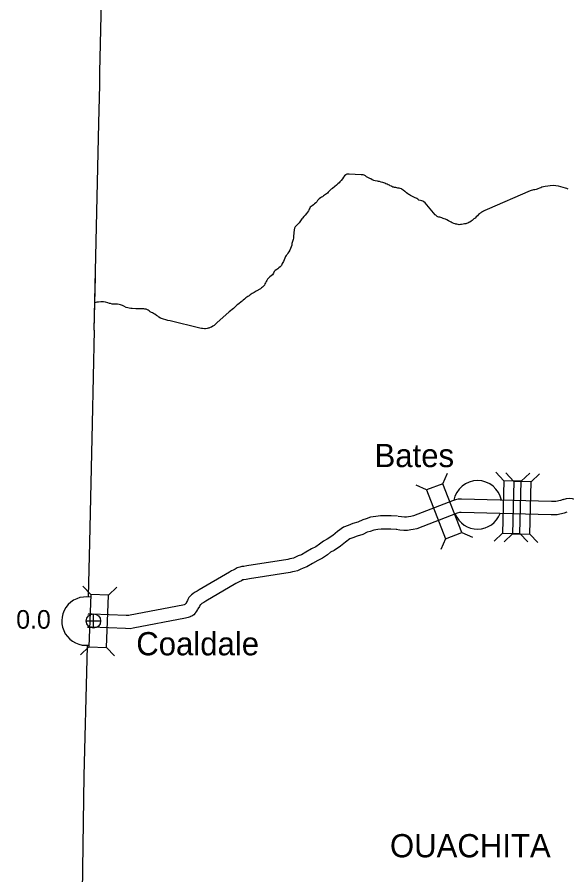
# Model space of a CAD drawing. Extents: x -939622 to -934245, y 1383184 to 1385301.
# Drawn here: x -936457.6 to -936420.2, y 1384298.8 to 1384357.3 of the extents above; entities that cross this region are included whole.
import ezdxf

# ---------------------------------------------------------------- set-up
doc = ezdxf.new("R2010")
doc.units = 0
for name, color, linetype in [('Level 1', 7, 'Continuous'), ('Level 10', 7, 'Continuous'), ('Level 2', 7, 'Continuous'), ('Level 20', 7, 'Continuous'), ('Level 24', 7, 'Continuous'), ('Level 25', 7, 'Continuous'), ('Level 26', 7, 'Continuous'), ('Level 8', 7, 'Continuous')]:
    doc.layers.add(name, color=color, linetype=linetype)

msp = doc.modelspace()

# ---------------------------------------------------------------- linework, layer by layer
at = {"layer": 'Level 1'}
for points in [[(-936452.361, 1384335.927), (-936452.042, 1384350.048), (-936451.974, 1384352.646), (-936451.962, 1384353.514), (-936451.499, 1384373.877)], [(-936452.361, 1384335.927), (-936452.279, 1384339.578)], [(-936452.361, 1384335.927), (-936452.497, 1384329.574), (-936452.676, 1384321.469), (-936452.759, 1384317.789)], [(-936452.835, 1384314.397), (-936452.855, 1384313.527), (-936453.061, 1384305.572)], [(-936453.061, 1384305.572), (-936453.175, 1384297.647)]]:
    msp.add_lwpolyline(points, dxfattribs=at)
at = {"layer": 'Level 10'}
for points in [[(-936420.42, 1384324.397), (-936420.61, 1384324.334), (-936420.935, 1384324.255), (-936421.229, 1384324.26), (-936427.346, 1384324.415), (-936427.412, 1384324.417), (-936427.566, 1384324.419), (-936427.749, 1384324.374), (-936427.952, 1384324.301), (-936430.624, 1384323.273), (-936430.801, 1384323.243), (-936430.948, 1384323.214), (-936431.093, 1384323.191), (-936431.225, 1384323.19), (-936431.437, 1384323.21), (-936431.656, 1384323.246)], [(-936420.42, 1384324.397), (-936420.207, 1384324.458), (-936420.026, 1384324.478), (-936419.812, 1384324.458), (-936419.656, 1384324.424), (-936419.471, 1384324.371), (-936419.305, 1384324.322), (-936419.188, 1384324.302), (-936418.95, 1384324.288), (-936418.616, 1384324.32)], [(-936431.697, 1384323.25), (-936432.133, 1384323.281), (-936432.55, 1384323.274), (-936432.867, 1384323.285), (-936433.176, 1384323.236), (-936433.54, 1384323.191), (-936433.838, 1384323.072), (-936434.065, 1384323.017), (-936434.399, 1384322.862), (-936434.75, 1384322.753), (-936435.066, 1384322.621), (-936435.38, 1384322.507), (-936435.782, 1384322.208), (-936436.116, 1384321.953), (-936436.491, 1384321.7), (-936436.753, 1384321.562), (-936437.009, 1384321.359), (-936437.276, 1384321.176), (-936437.568, 1384321.03), (-936437.938, 1384320.81), (-936438.254, 1384320.629), (-936438.471, 1384320.554), (-936438.697, 1384320.441), (-936438.794, 1384320.402), (-936438.912, 1384320.373), (-936439.042, 1384320.345), (-936439.182, 1384320.315), (-936441.961, 1384319.884), (-936442.159, 1384319.839), (-936442.304, 1384319.82), (-936442.437, 1384319.796), (-936442.626, 1384319.735), (-936442.75, 1384319.657), (-936442.906, 1384319.588), (-936443.007, 1384319.528), (-936443.149, 1384319.454), (-936445.208, 1384318.239), (-936445.347, 1384318.156), (-936445.524, 1384318.06), (-936445.631, 1384317.973), (-936445.731, 1384317.909), (-936445.81, 1384317.827), (-936445.909, 1384317.719), (-936445.98, 1384317.578), (-936446, 1384317.514), (-936446.08, 1384317.409), (-936446.128, 1384317.298), (-936446.137, 1384317.283), (-936446.174, 1384317.237), (-936446.18, 1384317.235), (-936446.221, 1384317.219), (-936446.318, 1384317.196), (-936449.906, 1384316.513), (-936449.999, 1384316.489), (-936450.185, 1384316.501), (-936452.494, 1384316.586), (-936452.642, 1384316.592), (-936452.771, 1384316.572), (-936452.774, 1384316.571)], [(-936420.188, 1384323.525), (-936420.362, 1384323.468), (-936420.835, 1384323.353), (-936421.248, 1384323.36), (-936427.372, 1384323.515), (-936427.432, 1384323.517), (-936427.463, 1384323.518), (-936427.489, 1384323.511), (-936427.638, 1384323.458), (-936430.385, 1384322.401), (-936430.638, 1384322.358), (-936430.789, 1384322.328), (-936431.02, 1384322.291), (-936431.266, 1384322.29), (-936431.551, 1384322.317), (-936431.8, 1384322.357)], [(-936431.759, 1384322.352), (-936432.156, 1384322.38), (-936432.559, 1384322.373), (-936432.812, 1384322.382), (-936433.051, 1384322.344), (-936433.314, 1384322.312), (-936433.564, 1384322.212), (-936433.766, 1384322.163), (-936434.074, 1384322.02), (-936434.443, 1384321.906), (-936434.74, 1384321.782), (-936434.949, 1384321.706), (-936435.24, 1384321.489), (-936435.591, 1384321.222), (-936436.028, 1384320.927), (-936436.259, 1384320.805), (-936436.475, 1384320.634), (-936436.818, 1384320.398), (-936437.137, 1384320.239), (-936437.484, 1384320.033), (-936437.88, 1384319.806), (-936438.122, 1384319.723), (-936438.329, 1384319.618), (-936438.518, 1384319.544), (-936438.709, 1384319.496), (-936438.854, 1384319.465), (-936439.019, 1384319.43), (-936441.793, 1384318.999), (-936442.001, 1384318.952), (-936442.166, 1384318.93), (-936442.218, 1384318.921), (-936442.243, 1384318.913), (-936442.326, 1384318.861), (-936442.492, 1384318.787), (-936442.569, 1384318.741), (-936442.712, 1384318.667), (-936444.749, 1384317.464), (-936444.901, 1384317.374), (-936445.021, 1384317.309), (-936445.103, 1384317.242), (-936445.151, 1384317.212), (-936445.185, 1384317.099), (-936445.299, 1384316.949), (-936445.319, 1384316.902), (-936445.386, 1384316.779), (-936445.455, 1384316.695), (-936445.488, 1384316.649), (-936445.583, 1384316.544), (-936445.71, 1384316.448), (-936445.79, 1384316.423), (-936445.834, 1384316.404), (-936445.953, 1384316.357), (-936446.13, 1384316.315), (-936449.709, 1384315.634), (-936449.914, 1384315.581), (-936450.232, 1384315.602), (-936452.529, 1384315.686), (-936452.59, 1384315.689), (-936452.677, 1384315.675), (-936452.777, 1384315.67), (-936452.815, 1384315.667)]]:
    msp.add_lwpolyline(points, dxfattribs=at)
at = {"layer": 'Level 2'}
for points in [[(-936431.532, 1384345.594), (-936431.601, 1384345.607), (-936431.688, 1384345.62), (-936431.748, 1384345.637), (-936431.812, 1384345.659), (-936431.904, 1384345.663), (-936431.961, 1384345.676), (-936432.019, 1384345.69), (-936432.094, 1384345.721), (-936432.127, 1384345.744), (-936432.206, 1384345.779), (-936432.258, 1384345.81), (-936432.342, 1384345.847), (-936432.418, 1384345.884), (-936432.502, 1384345.918), (-936432.566, 1384345.953), (-936432.71, 1384345.991), (-936432.822, 1384346.028), (-936432.936, 1384346.058), (-936433.005, 1384346.074), (-936433.068, 1384346.079), (-936433.23, 1384346.114), (-936433.311, 1384346.136), (-936433.372, 1384346.158), (-936433.423, 1384346.172), (-936433.523, 1384346.239), (-936433.601, 1384346.261), (-936433.729, 1384346.33), (-936433.817, 1384346.394), (-936433.89, 1384346.446), (-936433.932, 1384346.481), (-936433.984, 1384346.504), (-936434.038, 1384346.517), (-936434.101, 1384346.516), (-936434.181, 1384346.511), (-936434.989, 1384346.557), (-936435.052, 1384346.562), (-936435.106, 1384346.563), (-936435.136, 1384346.56), (-936435.16, 1384346.565), (-936435.201, 1384346.546), (-936435.236, 1384346.524), (-936435.309, 1384346.453), (-936435.376, 1384346.362), (-936435.463, 1384346.252), (-936435.55, 1384346.135), (-936435.625, 1384346.052), (-936435.689, 1384345.985), (-936435.771, 1384345.914), (-936435.865, 1384345.812), (-936435.979, 1384345.72), (-936436.14, 1384345.599), (-936436.219, 1384345.537), (-936436.263, 1384345.497), (-936436.319, 1384345.45), (-936436.369, 1384345.404), (-936436.424, 1384345.337), (-936436.479, 1384345.275), (-936436.543, 1384345.22), (-936436.599, 1384345.182), (-936436.682, 1384345.129), (-936436.74, 1384345.089), (-936436.817, 1384345.03), (-936436.873, 1384344.995), (-936436.952, 1384344.945), (-936437.04, 1384344.883), (-936437.104, 1384344.819), (-936437.148, 1384344.763), (-936437.206, 1384344.684), (-936437.267, 1384344.616), (-936437.361, 1384344.539), (-936437.434, 1384344.483), (-936437.528, 1384344.415), (-936437.58, 1384344.366), (-936437.642, 1384344.31), (-936437.676, 1384344.255), (-936437.722, 1384344.173), (-936437.739, 1384344.116), (-936437.773, 1384344.061), (-936437.834, 1384343.969), (-936437.894, 1384343.887), (-936437.996, 1384343.761), (-936438.075, 1384343.684), (-936438.168, 1384343.574), (-936438.214, 1384343.519), (-936438.269, 1384343.454), (-936438.316, 1384343.393), (-936438.362, 1384343.326), (-936438.408, 1384343.244), (-936438.472, 1384343.176), (-936438.548, 1384343.102), (-936438.612, 1384343.047), (-936438.676, 1384342.97), (-936438.696, 1384342.93), (-936438.719, 1384342.882), (-936438.727, 1384342.846), (-936438.738, 1384342.803), (-936438.782, 1384342.31), (-936438.798, 1384342.195), (-936438.811, 1384342.12), (-936438.827, 1384342.048)], [(-936431.532, 1384345.594), (-936431.601, 1384345.607), (-936431.688, 1384345.62), (-936431.748, 1384345.637), (-936431.812, 1384345.659), (-936431.904, 1384345.663), (-936431.961, 1384345.676), (-936432.019, 1384345.69), (-936432.094, 1384345.721), (-936432.127, 1384345.744), (-936432.206, 1384345.779), (-936432.258, 1384345.81), (-936432.342, 1384345.847), (-936432.418, 1384345.884), (-936432.502, 1384345.918), (-936432.566, 1384345.953), (-936432.71, 1384345.991), (-936432.822, 1384346.028), (-936432.936, 1384346.058), (-936433.005, 1384346.074), (-936433.068, 1384346.079), (-936433.23, 1384346.114), (-936433.311, 1384346.136), (-936433.372, 1384346.158), (-936433.423, 1384346.172), (-936433.523, 1384346.239), (-936433.601, 1384346.261), (-936433.729, 1384346.33), (-936433.817, 1384346.394), (-936433.89, 1384346.446), (-936433.932, 1384346.481), (-936433.984, 1384346.504), (-936434.038, 1384346.517), (-936434.101, 1384346.516), (-936434.181, 1384346.511), (-936434.989, 1384346.557), (-936435.052, 1384346.562), (-936435.106, 1384346.563), (-936435.136, 1384346.56), (-936435.16, 1384346.565), (-936435.201, 1384346.546), (-936435.236, 1384346.524), (-936435.309, 1384346.453), (-936435.376, 1384346.362), (-936435.463, 1384346.252), (-936435.55, 1384346.135), (-936435.625, 1384346.052), (-936435.689, 1384345.985), (-936435.771, 1384345.914), (-936435.865, 1384345.812), (-936435.979, 1384345.72), (-936436.14, 1384345.599), (-936436.219, 1384345.537), (-936436.263, 1384345.497), (-936436.319, 1384345.45), (-936436.369, 1384345.404), (-936436.424, 1384345.337), (-936436.479, 1384345.275), (-936436.543, 1384345.22), (-936436.599, 1384345.182), (-936436.682, 1384345.129), (-936436.74, 1384345.089), (-936436.817, 1384345.03), (-936436.873, 1384344.995), (-936436.952, 1384344.945), (-936437.04, 1384344.883), (-936437.104, 1384344.819), (-936437.148, 1384344.763), (-936437.206, 1384344.684), (-936437.267, 1384344.616), (-936437.361, 1384344.539), (-936437.434, 1384344.483), (-936437.528, 1384344.415), (-936437.58, 1384344.366), (-936437.642, 1384344.31), (-936437.676, 1384344.255), (-936437.722, 1384344.173), (-936437.739, 1384344.116), (-936437.773, 1384344.061), (-936437.834, 1384343.969), (-936437.894, 1384343.887), (-936437.996, 1384343.761), (-936438.075, 1384343.684), (-936438.168, 1384343.574), (-936438.214, 1384343.519), (-936438.269, 1384343.454), (-936438.316, 1384343.393), (-936438.362, 1384343.326), (-936438.408, 1384343.244), (-936438.472, 1384343.176), (-936438.548, 1384343.102), (-936438.612, 1384343.047), (-936438.676, 1384342.97), (-936438.696, 1384342.93), (-936438.719, 1384342.882), (-936438.727, 1384342.846), (-936438.738, 1384342.803), (-936438.782, 1384342.31), (-936438.798, 1384342.195), (-936438.811, 1384342.12), (-936438.827, 1384342.048)], [(-936420.086, 1384345.546), (-936420.185, 1384345.582), (-936420.272, 1384345.604), (-936420.577, 1384345.708), (-936420.751, 1384345.746), (-936420.919, 1384345.777), (-936421.075, 1384345.795), (-936421.31, 1384345.768), (-936421.471, 1384345.746), (-936421.644, 1384345.715), (-936421.763, 1384345.7), (-936421.87, 1384345.679), (-936421.95, 1384345.641), (-936422.05, 1384345.603), (-936422.142, 1384345.562), (-936422.198, 1384345.539), (-936422.272, 1384345.519), (-936422.368, 1384345.502), (-936422.439, 1384345.497), (-936422.522, 1384345.477), (-936422.603, 1384345.454), (-936422.683, 1384345.425), (-936425.61, 1384344.15), (-936425.758, 1384344.089), (-936425.853, 1384344.048), (-936425.923, 1384344.01), (-936425.985, 1384343.973), (-936426.041, 1384343.932), (-936426.079, 1384343.907), (-936426.12, 1384343.873), (-936426.184, 1384343.815), (-936426.272, 1384343.72), (-936426.354, 1384343.652), (-936426.43, 1384343.575), (-936426.5, 1384343.516), (-936426.585, 1384343.454), (-936426.629, 1384343.402), (-936426.696, 1384343.355), (-936426.773, 1384343.305), (-936426.846, 1384343.261), (-936426.92, 1384343.226), (-936427.006, 1384343.197), (-936427.06, 1384343.19), (-936427.149, 1384343.173), (-936427.241, 1384343.156), (-936427.345, 1384343.141), (-936427.429, 1384343.127), (-936427.512, 1384343.122), (-936427.581, 1384343.132), (-936427.665, 1384343.148), (-936427.734, 1384343.159), (-936427.783, 1384343.172), (-936427.861, 1384343.195), (-936427.982, 1384343.258), (-936428.063, 1384343.286), (-936428.151, 1384343.341), (-936428.227, 1384343.375), (-936428.357, 1384343.45), (-936428.445, 1384343.49), (-936428.532, 1384343.517), (-936428.599, 1384343.549), (-936428.698, 1384343.579), (-936428.764, 1384343.611), (-936428.825, 1384343.63), (-936428.894, 1384343.641), (-936428.972, 1384343.669), (-936429.011, 1384343.692), (-936429.057, 1384343.724), (-936429.094, 1384343.774), (-936429.137, 1384343.806), (-936429.823, 1384344.606), (-936429.914, 1384344.685), (-936429.993, 1384344.722), (-936430.044, 1384344.747), (-936430.138, 1384344.778), (-936430.246, 1384344.803), (-936430.276, 1384344.823), (-936430.316, 1384344.858), (-936430.392, 1384344.904), (-936430.446, 1384344.93), (-936430.501, 1384344.959), (-936430.54, 1384344.979), (-936430.588, 1384344.998), (-936430.645, 1384345.018), (-936430.691, 1384345.044), (-936430.767, 1384345.081), (-936430.833, 1384345.122), (-936430.882, 1384345.156), (-936430.937, 1384345.188), (-936431.012, 1384345.234), (-936431.104, 1384345.301), (-936431.156, 1384345.351), (-936431.216, 1384345.394), (-936431.32, 1384345.485), (-936431.384, 1384345.528), (-936431.445, 1384345.563), (-936431.532, 1384345.594)], [(-936420.086, 1384345.546), (-936420.185, 1384345.582), (-936420.272, 1384345.604), (-936420.577, 1384345.708), (-936420.751, 1384345.746), (-936420.919, 1384345.777), (-936421.075, 1384345.795), (-936421.31, 1384345.768), (-936421.471, 1384345.746), (-936421.644, 1384345.715), (-936421.763, 1384345.7), (-936421.87, 1384345.679), (-936421.95, 1384345.641), (-936422.05, 1384345.603), (-936422.142, 1384345.562), (-936422.198, 1384345.539), (-936422.272, 1384345.519), (-936422.368, 1384345.502), (-936422.439, 1384345.497), (-936422.522, 1384345.477), (-936422.603, 1384345.454), (-936422.683, 1384345.425), (-936425.61, 1384344.15), (-936425.758, 1384344.089), (-936425.853, 1384344.048), (-936425.923, 1384344.01), (-936425.985, 1384343.973), (-936426.041, 1384343.932), (-936426.079, 1384343.907), (-936426.12, 1384343.873), (-936426.184, 1384343.815), (-936426.272, 1384343.72), (-936426.354, 1384343.652), (-936426.43, 1384343.575), (-936426.5, 1384343.516), (-936426.585, 1384343.454), (-936426.629, 1384343.402), (-936426.696, 1384343.355), (-936426.773, 1384343.305), (-936426.846, 1384343.261), (-936426.92, 1384343.226), (-936427.006, 1384343.197), (-936427.06, 1384343.19), (-936427.149, 1384343.173), (-936427.241, 1384343.156), (-936427.345, 1384343.141), (-936427.429, 1384343.127), (-936427.512, 1384343.122), (-936427.581, 1384343.132), (-936427.665, 1384343.148), (-936427.734, 1384343.159), (-936427.783, 1384343.172), (-936427.861, 1384343.195), (-936427.982, 1384343.258), (-936428.063, 1384343.286), (-936428.151, 1384343.341), (-936428.227, 1384343.375), (-936428.357, 1384343.45), (-936428.445, 1384343.49), (-936428.532, 1384343.517), (-936428.599, 1384343.549), (-936428.698, 1384343.579), (-936428.764, 1384343.611), (-936428.825, 1384343.63), (-936428.894, 1384343.641), (-936428.972, 1384343.669), (-936429.011, 1384343.692), (-936429.057, 1384343.724), (-936429.094, 1384343.774), (-936429.137, 1384343.806), (-936429.823, 1384344.606), (-936429.914, 1384344.685), (-936429.993, 1384344.722), (-936430.044, 1384344.747), (-936430.138, 1384344.778), (-936430.246, 1384344.803), (-936430.276, 1384344.823), (-936430.316, 1384344.858), (-936430.392, 1384344.904), (-936430.446, 1384344.93), (-936430.501, 1384344.959), (-936430.54, 1384344.979), (-936430.588, 1384344.998), (-936430.645, 1384345.018), (-936430.691, 1384345.044), (-936430.767, 1384345.081), (-936430.833, 1384345.122), (-936430.882, 1384345.156), (-936430.937, 1384345.188), (-936431.012, 1384345.234), (-936431.104, 1384345.301), (-936431.156, 1384345.351), (-936431.216, 1384345.394), (-936431.32, 1384345.485), (-936431.384, 1384345.528), (-936431.445, 1384345.563), (-936431.532, 1384345.594)], [(-936438.827, 1384342.048), (-936438.846, 1384341.972), (-936438.871, 1384341.911), (-936438.89, 1384341.833), (-936438.909, 1384341.736), (-936438.945, 1384341.609), (-936438.99, 1384341.491), (-936439.038, 1384341.394), (-936439.113, 1384341.266), (-936439.167, 1384341.181), (-936439.228, 1384341.092), (-936439.28, 1384341.019), (-936439.323, 1384340.949), (-936439.383, 1384340.851), (-936439.419, 1384340.736), (-936439.479, 1384340.612), (-936439.554, 1384340.481), (-936439.613, 1384340.353), (-936439.695, 1384340.255), (-936439.776, 1384340.178), (-936439.856, 1384340.116), (-936439.92, 1384340.064), (-936440.029, 1384340.004), (-936440.099, 1384339.924), (-936440.153, 1384339.83), (-936440.219, 1384339.714), (-936440.298, 1384339.649), (-936440.392, 1384339.56), (-936440.465, 1384339.492), (-936440.552, 1384339.406), (-936440.607, 1384339.32), (-936440.653, 1384339.25), (-936440.702, 1384339.168), (-936440.73, 1384339.083), (-936440.77, 1384339.004), (-936440.84, 1384338.924), (-936440.889, 1384338.875), (-936440.96, 1384338.822), (-936441.045, 1384338.76), (-936441.319, 1384338.594), (-936441.46, 1384338.498), (-936441.592, 1384338.426), (-936441.731, 1384338.341), (-936441.813, 1384338.279), (-936441.893, 1384338.232), (-936442.031, 1384338.133), (-936442.13, 1384338.049), (-936442.218, 1384337.981), (-936442.288, 1384337.919), (-936442.344, 1384337.867), (-936442.511, 1384337.731), (-936442.62, 1384337.656), (-936442.716, 1384337.567), (-936442.876, 1384337.407), (-936443.161, 1384337.178), (-936443.389, 1384336.971), (-936443.98, 1384336.455), (-936444.126, 1384336.313), (-936444.199, 1384336.249), (-936444.275, 1384336.199), (-936444.364, 1384336.149), (-936444.459, 1384336.116), (-936444.547, 1384336.072), (-936444.595, 1384336.068), (-936444.669, 1384336.045), (-936444.768, 1384336.034), (-936444.854, 1384336.029), (-936444.974, 1384336.053), (-936445.055, 1384336.06), (-936445.157, 1384336.081), (-936447.195, 1384336.569), (-936447.354, 1384336.601), (-936447.484, 1384336.631), (-936447.643, 1384336.675), (-936447.712, 1384336.697), (-936447.848, 1384336.745), (-936447.961, 1384336.832), (-936448.019, 1384336.885), (-936448.113, 1384336.94), (-936448.234, 1384337.015), (-936448.319, 1384337.073), (-936448.389, 1384337.11), (-936448.461, 1384337.148), (-936448.543, 1384337.188), (-936448.619, 1384337.255), (-936448.689, 1384337.304), (-936448.828, 1384337.364), (-936448.912, 1384337.371), (-936448.978, 1384337.381), (-936449.038, 1384337.386), (-936449.155, 1384337.398), (-936449.235, 1384337.396), (-936449.319, 1384337.397), (-936449.4, 1384337.395), (-936449.522, 1384337.392), (-936449.767, 1384337.404), (-936449.872, 1384337.407), (-936449.974, 1384337.429), (-936450.068, 1384337.457), (-936450.188, 1384337.487), (-936450.337, 1384337.582)], [(-936438.827, 1384342.048), (-936438.846, 1384341.972), (-936438.871, 1384341.911), (-936438.89, 1384341.833), (-936438.909, 1384341.736), (-936438.945, 1384341.609), (-936438.99, 1384341.491), (-936439.038, 1384341.394), (-936439.113, 1384341.266), (-936439.167, 1384341.181), (-936439.228, 1384341.092), (-936439.28, 1384341.019), (-936439.323, 1384340.949), (-936439.383, 1384340.851), (-936439.419, 1384340.736), (-936439.479, 1384340.612), (-936439.554, 1384340.481), (-936439.613, 1384340.353), (-936439.695, 1384340.255), (-936439.776, 1384340.178), (-936439.856, 1384340.116), (-936439.92, 1384340.064), (-936440.029, 1384340.004), (-936440.099, 1384339.924), (-936440.153, 1384339.83), (-936440.219, 1384339.714), (-936440.298, 1384339.649), (-936440.392, 1384339.56), (-936440.465, 1384339.492), (-936440.552, 1384339.406), (-936440.607, 1384339.32), (-936440.653, 1384339.25), (-936440.702, 1384339.168), (-936440.73, 1384339.083), (-936440.77, 1384339.004), (-936440.84, 1384338.924), (-936440.889, 1384338.875), (-936440.96, 1384338.822), (-936441.045, 1384338.76), (-936441.319, 1384338.594), (-936441.46, 1384338.498), (-936441.592, 1384338.426), (-936441.731, 1384338.341), (-936441.813, 1384338.279), (-936441.893, 1384338.232), (-936442.031, 1384338.133), (-936442.13, 1384338.049), (-936442.218, 1384337.981), (-936442.288, 1384337.919), (-936442.344, 1384337.867), (-936442.511, 1384337.731), (-936442.62, 1384337.656), (-936442.716, 1384337.567), (-936442.876, 1384337.407), (-936443.161, 1384337.178), (-936443.389, 1384336.971), (-936443.98, 1384336.455), (-936444.126, 1384336.313), (-936444.199, 1384336.249), (-936444.275, 1384336.199), (-936444.364, 1384336.149), (-936444.459, 1384336.116), (-936444.547, 1384336.072), (-936444.595, 1384336.068), (-936444.669, 1384336.045), (-936444.768, 1384336.034), (-936444.854, 1384336.029), (-936444.974, 1384336.053), (-936445.055, 1384336.06), (-936445.157, 1384336.081), (-936447.195, 1384336.569), (-936447.354, 1384336.601), (-936447.484, 1384336.631), (-936447.643, 1384336.675), (-936447.712, 1384336.697), (-936447.848, 1384336.745), (-936447.961, 1384336.832), (-936448.019, 1384336.885), (-936448.113, 1384336.94), (-936448.234, 1384337.015), (-936448.319, 1384337.073), (-936448.389, 1384337.11), (-936448.461, 1384337.148), (-936448.543, 1384337.188), (-936448.619, 1384337.255), (-936448.689, 1384337.304), (-936448.828, 1384337.364), (-936448.912, 1384337.371), (-936448.978, 1384337.381), (-936449.038, 1384337.386), (-936449.155, 1384337.398), (-936449.235, 1384337.396), (-936449.319, 1384337.397), (-936449.4, 1384337.395), (-936449.522, 1384337.392), (-936449.767, 1384337.404), (-936449.872, 1384337.407), (-936449.974, 1384337.429), (-936450.068, 1384337.457), (-936450.188, 1384337.487), (-936450.337, 1384337.582)], [(-936450.337, 1384337.582), (-936450.433, 1384337.619), (-936450.575, 1384337.657), (-936450.653, 1384337.689), (-936450.779, 1384337.709), (-936450.875, 1384337.713), (-936451.012, 1384337.707), (-936451.129, 1384337.707), (-936451.237, 1384337.743), (-936451.312, 1384337.76), (-936451.432, 1384337.793), (-936451.577, 1384337.837), (-936451.727, 1384337.866), (-936451.832, 1384337.876), (-936451.916, 1384337.874), (-936452.073, 1384337.849), (-936452.166, 1384337.847), (-936452.234, 1384337.824), (-936452.341, 1384337.803)], [(-936450.337, 1384337.582), (-936450.433, 1384337.619), (-936450.575, 1384337.657), (-936450.653, 1384337.689), (-936450.779, 1384337.709), (-936450.875, 1384337.713), (-936451.012, 1384337.707), (-936451.129, 1384337.707), (-936451.237, 1384337.743), (-936451.312, 1384337.76), (-936451.432, 1384337.793), (-936451.577, 1384337.837), (-936451.727, 1384337.866), (-936451.832, 1384337.876), (-936451.916, 1384337.874), (-936452.073, 1384337.849), (-936452.166, 1384337.847), (-936452.234, 1384337.824), (-936452.341, 1384337.803)]]:
    msp.add_lwpolyline(points, dxfattribs=at)
at = {"layer": 'Level 20'}
for p, q in [((-936428.613, 1384325.474), (-936428.292, 1384326.198)), ((-936424.467, 1384325.674), (-936425.012, 1384326.248)), ((-936423.79, 1384325.63), (-936424.336, 1384326.204)), ((-936423.279, 1384325.644), (-936422.705, 1384326.19)), ((-936422.603, 1384325.6), (-936422.029, 1384326.145)), ((-936429.722, 1384325.047), (-936430.446, 1384325.369)), ((-936427.333, 1384322.148), (-936426.61, 1384321.826)), ((-936424.557, 1384322.112), (-936425.131, 1384321.566)), ((-936423.369, 1384322.081), (-936422.824, 1384321.507)), ((-936428.442, 1384321.721), (-936428.764, 1384320.997)), ((-936423.881, 1384322.067), (-936424.455, 1384321.521)), ((-936422.693, 1384322.037), (-936422.147, 1384321.463)), ((-936452.581, 1384317.922), (-936453.12, 1384318.502)), ((-936451.394, 1384317.878), (-936450.813, 1384318.417)), ((-936452.711, 1384314.36), (-936453.291, 1384313.821)), ((-936451.524, 1384314.317), (-936450.985, 1384313.737))]:
    msp.add_line(p, q, dxfattribs=at)
for points in [[(-936424.467, 1384325.674), (-936424.557, 1384322.112), (-936423.369, 1384322.081), (-936423.279, 1384325.644)], [(-936423.79, 1384325.63), (-936423.881, 1384322.067), (-936422.693, 1384322.037), (-936422.603, 1384325.6)], [(-936429.722, 1384325.047), (-936428.442, 1384321.721), (-936427.333, 1384322.148), (-936428.613, 1384325.474)], [(-936451.524, 1384314.317), (-936451.394, 1384317.878), (-936452.581, 1384317.922), (-936452.711, 1384314.36)]]:
    msp.add_lwpolyline(points, close=True, dxfattribs=at)
at = {"layer": 'Level 24'}
for centre, start, end in [((-936426.253, 1384324.033), 10.81324, 169.22083), ((-936426.253, 1384324.033), 202.25994, 338.79706), ((-936452.918, 1384316.111), 79.46015, 277.65406)]:
    msp.add_arc(centre, 1.65, start, end, dxfattribs=at)
at = {"layer": 'Level 26'}
for p, q in [((-936452.406, 1384315.63), (-936452.406, 1384316.605)), ((-936452.893, 1384316.118), (-936451.918, 1384316.118))]:
    msp.add_line(p, q, dxfattribs=at)
msp.add_circle((-936452.406, 1384316.118), 0.487, dxfattribs=at)

# ---------------------------------------------------------------- texts
at = {"layer": 'Level 24'}
for s, p in [('Bates', (-936433.271, 1384326.603)), ('Coaldale', (-936449.493, 1384313.777))]:
    msp.add_text(s, height=1.584, dxfattribs=at).set_placement(p)
at = {"layer": 'Level 25'}
msp.add_text('0.0', height=1.2672, dxfattribs=at).set_placement((-936457.667, 1384315.593))
at = {"layer": 'Level 8'}
msp.add_text('OUACHITA', height=1.584, dxfattribs=at).set_placement((-936432.222, 1384300.013))

doc.saveas('drawing.dxf')
